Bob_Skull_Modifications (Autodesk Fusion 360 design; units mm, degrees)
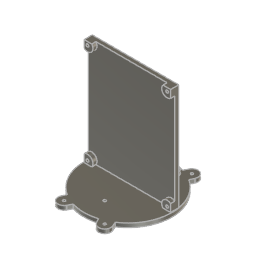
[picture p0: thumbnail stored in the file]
sketch "Bottom" plane through (0, 0, 0) normal (0, 0, 1) x axis (1, 0, 0)
  line L1 (-14.7916, -31.7208) -> (0, 0)
  line L2 (50, 0) -> (0, 0)
  line L3 (-8.961, -31.2402) -> (-10.3196, -33.9571)
  line L4 (-18.1121, -26.9852) -> (-19.331, -29.6245)
  line L5 (0, 13.6394) -> (0, 0)
  line L6 (12.7532, 0) -> (0, 0)
  line L7 (8.961, -31.2402) -> (10.3196, -33.9571)
  line L8 (18.1121, -26.9852) -> (19.331, -29.6245)
  line L9 (8.961, 31.2402) -> (10.3196, 33.9571)
  line L10 (18.1121, 26.9852) -> (19.331, 29.6245)
  line L11 (-8.961, 31.2402) -> (-10.3196, 33.9571)
  line L12 (-18.1121, 26.9852) -> (-19.331, 29.6245)
  line L13 (-9.4082, -31.0166) -> (-10.7668, -33.7335)
  line L14 (-17.6582, -27.1948) -> (-18.877, -29.8341)
  line L15 (-9.2212, -30.6426) -> (-9.4082, -31.0166)
  line L16 (-17.4782, -26.8051) -> (-17.6582, -27.1948)
  line L17 (17.4782, -26.8051) -> (17.6582, -27.1948)
  line L18 (9.2212, -30.6426) -> (9.4082, -31.0166)
  line L19 (9.4082, -31.0166) -> (10.7668, -33.7335)
  line L20 (17.6582, -27.1948) -> (18.877, -29.8341)
  line L21 (-17.4782, 26.8051) -> (-17.6582, 27.1948)
  line L22 (-9.2212, 30.6426) -> (-9.4082, 31.0166)
  line L23 (9.2212, 30.6426) -> (9.4082, 31.0166)
  line L24 (17.4782, 26.8051) -> (17.6582, 27.1948)
  line L25 (17.6582, 27.1948) -> (18.877, 29.8341)
  line L26 (9.4082, 31.0166) -> (10.7668, 33.7335)
  line L27 (-9.4082, 31.0166) -> (-10.7668, 33.7335)
  line L28 (-17.6582, 27.1948) -> (-18.877, 29.8341)
  line L29 (-31.5, 5.5) -> (31.5, 5.5)
  line L30 (-31.5, 2.5) -> (-31.5, 5.5)
  line L31 (31.5, 2.5) -> (-31.5, 2.5)
  line L32 (31.5, 5.5) -> (31.5, 2.5)
  line L33 (-31.5, 2.5) -> (31.5, 5.5)
  line L34 (31.5, 2.5) -> (-31.5, 5.5)
  line L35 (0, 4) -> (0, 0)
  line L36 (0, 25) -> (0, 0)
  line L37 (-3.5, 27) -> (3.5, 27)
  line L38 (-3.5, 23) -> (-3.5, 27)
  line L39 (3.5, 23) -> (-3.5, 23)
  line L40 (3.5, 27) -> (3.5, 23)
  line L41 (-3.5, 23) -> (3.5, 27)
  line L42 (3.5, 23) -> (-3.5, 27)
  line L43 (5.5, 21) -> (-5.5, 21)
  line L44 (5.5, 29) -> (5.5, 21)
  line L45 (-5.5, 29) -> (5.5, 29)
  line L46 (-5.5, 21) -> (-5.5, 29)
  line L47 (-7.5, 25) -> (0, 25)
  line L48 (0, 31) -> (0, 32)
  line L49 (0, -17) -> (0, 0)
  curve K1
  curve K2
  curve K3
  curve K4
  curve K5
  curve K6
  curve K7
  curve K8
  circle C1 centre (0, 0) radius 32.5
  circle C2 centre (-14.7916, -31.7208) radius 5
  circle C3 centre (-14.7916, -31.7208) radius 0.9
  circle C4 centre (14.7916, -31.7208) radius 5
  circle C5 centre (14.7916, -31.7208) radius 0.9
  circle C6 centre (14.7916, 31.7208) radius 5
  circle C7 centre (14.7916, 31.7208) radius 0.9
  circle C8 centre (-14.7916, 31.7208) radius 5
  circle C9 centre (-14.7916, 31.7208) radius 0.9
  circle C10 centre (0, 0) radius 32
  circle C11 centre (-14.7916, -31.7208) radius 4.5
  circle C12 centre (14.7916, -31.7208) radius 4.5
  circle C13 centre (14.7916, 31.7208) radius 4.5
  circle C14 centre (-14.7916, 31.7208) radius 4.5
  circle C15 centre (-7.5, 25) radius 1
  circle C16 centre (7.5, 25) radius 1
  circle C17 centre (-7.5, 25) radius 4
  circle C18 centre (7.5, 25) radius 4
  circle C19 centre (0, 31) radius 2
  circle C20 centre (0, -17) radius 12.5
  circle C21 centre (0, -17) radius 1
  point P1 (0, 0)
  point P2 (0, 0)
  point P3 (0, 0)
  point P4 (-14.7916, -31.7208)
  point P6 (-14.7916, -31.7208)
  point P8 (-10.3196, -33.9571)
  point P9 (-8.961, -31.2402)
  point P10 (-19.331, -29.6245)
  point P11 (-18.1121, -26.9852)
  point P12 (0, 0)
  point P14 (0, 0)
  point P15 (12.7532, 0)
  point P17 (10.3196, -33.9571)
  point P18 (8.961, -31.2402)
  point P19 (19.331, -29.6245)
  point P20 (18.1121, -26.9852)
  point P28 (-10.3196, 33.9571)
  point P29 (-8.961, 31.2402)
  point P32 (-19.331, 29.6245)
  point P33 (-18.1121, 26.9852)
  point P23 (10.3196, 33.9571)
  point P24 (8.961, 31.2402)
  point P25 (19.331, 29.6245)
  point P26 (18.1121, 26.9852)
  point P40 (-9.2212, -30.6426)
  point P41 (-17.4782, -26.8051)
  point P36 (-10.7668, -33.7335)
  point P46 (10.7668, -33.7335)
  point P37 (-9.4082, -31.0166)
  point P44 (9.4082, -31.0166)
  point P38 (-18.877, -29.8341)
  point P48 (18.877, -29.8341)
  point P39 (-17.6582, -27.1948)
  point P42 (17.6582, -27.1948)
  point P45 (9.2212, -30.6426)
  point P43 (17.4782, -26.8051)
  point P60 (-10.7668, 33.7335)
  point P51 (-9.4082, 31.0166)
  point P62 (-18.877, 29.8341)
  point P49 (-17.6582, 27.1948)
  point P52 (-9.2212, 30.6426)
  point P50 (-17.4782, 26.8051)
  point P55 (17.6582, 27.1948)
  point P56 (17.4782, 26.8051)
  point P53 (9.4082, 31.0166)
  point P54 (9.2212, 30.6426)
  point P59 (10.7668, 33.7335)
  point P57 (18.877, 29.8341)
  point P67 (0, 4)
  point P68 (0, 0)
  point P69 (0, 4)
  point P70 (0, 0)
  point P76 (0, 25)
  point P71 (0, 25)
  point P81 (0, 25)
  point P82 (-7.5, 25)
  point P83 (-7.5, 25)
  point P88 (0, 32)
  point P87 (0, 31)
  point P89 (0, 31)
  point P90 (0, 0)
  point P91 (0, -17)
  point P92 (0, -17)
  point P65 (-31.5, 2.5)
  point P66 (31.5, 2.5)
  point P64 (-31.5, 5.5)
  point P74 (-3.5, 23)
  point P75 (3.5, 23)
  point P73 (-3.5, 27)
  coincident P1 P2
  horizontal L2
  coincident P2 P3
  coincident P4 P6
  concentric C2 C3
  coincident C2 P8
  coincident C1 P9
  tangent C2 L3
  coincident C2 P10
  coincident C1 P11
  tangent C2 L4
  coincident P2 P12
  perpendicular L2 L5
  coincident P2 P14
  coincident L2 P15
  symmetric C2 L5 C4
  symmetric C3 L5 C5
  symmetric P8 L5 P17
  symmetric P9 L5 P18
  symmetric P10 L5 P19
  symmetric P11 L5 P20
  symmetric C2 L6 C8
  symmetric C3 L6 C9
  symmetric P8 L6 P28
  symmetric P9 L6 P29
  symmetric P10 L6 P32
  symmetric P11 L6 P33
  symmetric L6 C4 C6
  symmetric L6 P17 P23
  symmetric L6 P18 P24
  symmetric L6 P19 P25
  symmetric L6 P20 P26
  symmetric L6 C5 C7
  coincident C10 P40
  parallel L13 L15
  coincident C10 P41
  parallel L14 L16
  symmetric L5 C11 C12
  symmetric L5 P36 P46
  symmetric L5 P37 P44
  symmetric L5 P38 P48
  symmetric L5 P39 P42
  symmetric L5 P40 P45
  symmetric L5 P41 P43
  symmetric L2 C11 C14
  symmetric L2 P36 P60
  symmetric L2 P37 P51
  symmetric L2 P38 P62
  symmetric L2 P39 P49
  symmetric L2 P40 P52
  symmetric L2 P41 P50
  symmetric L2 P42 P55
  symmetric L2 P43 P56
  symmetric L2 P44 P53
  symmetric L2 P45 P54
  symmetric L2 P46 P59
  symmetric L2 C12 C13
  symmetric L2 P48 P57
  horizontal L29
  perpendicular L29 L30
  parallel L29 L31
  parallel L30 L32
  coincident L33 P67
  coincident L34 P67
  coincident P2 P68
  coincident P67 P69
  perpendicular L31 L35
  coincident P1 P70
  perpendicular L2 L36
  horizontal L37
  perpendicular L37 L38
  parallel L37 L39
  parallel L38 L40
  coincident L41 P76
  coincident L42 P76
  coincident P71 P76
  coincident P76 P81
  perpendicular L46 L47
  coincident P82 P83
  symmetric L36 C15 C16
  symmetric L36 C17 C18
  coincident C10 P88
  coincident P87 P89
  vertical L48
  tangent L45 C19
  coincident P1 P90
  perpendicular L6 L49
  coincident P91 P92
  concentric C20 C21
  dimension "d1" diameter C1 = 65
  dimension "d18" angle L1 L2 = 115 (= "90 deg + 25 deg")
  dimension "d19" distance P3 P4 = 35
  dimension "d20" diameter C2 = 10
  dimension "d21" diameter C3 = 1.8
  dimension "d27" = -0.5
  dimension "d28" = -0.5
  dimension "d29" = -0.5
  dimension "d30" = 0.5
  dimension "d33" distance P65 P66 = 63
  dimension "d34" distance P64 P65 = 3
  dimension "d35" distance P68 P69 = 4
  dimension "d55" distance P70 P71 = 25
  dimension "d56" distance P74 P75 = 7
  dimension "d57" distance P73 P74 = 4
  dimension "d58" = 2
  dimension "d59" distance P81 P82 = 7.5 (= "( 15 / 2 ) * 1 mm")
  dimension "d60" diameter C15 = 2
  dimension "d61" = 3
  dimension "d74" diameter C19 = 4
  dimension "d75" distance P90 P91 = 17
  dimension "d76" diameter C20 = 25
  dimension "d77" diameter C21 = 2
  dimension "d81" Text1-Height = 4
  dimension "d83" Text2-Height = 4
extrude "Extrude1" new body sketch "Bottom" profile of C1 along normal blind 134 bodies "Opening"
fillet "Fillet1" radius 32.5 (= "d1 / 2")
sketch "Eyes" plane through (0, 0, 0) normal (0, 1, 0) x axis (1, 0, 0)
  line L1 (0, -80) -> (0, 0)
  line L2 (-30, -80) -> (0, -80)
  line L3 (22, -80) -> (0, -80)
  circle C1 centre (-30, -80) radius 3.5
  circle C2 centre (22, -80) radius 3.5
  point P1 (0, 0)
  point P2 (0, 0)
  point P4 (-30, -80)
  point P5 (-30, -80)
  point P6 (22, -80)
  point P7 (22, -80)
  point P3 (0, -80)
  coincident P1 P2
  vertical L1
  perpendicular L1 L2
  coincident P4 P5
  perpendicular L1 L3
  coincident P6 P7
  dimension "d6" distance P2 P3 = 80
  dimension "d7" distance P3 P4 = 30
  dimension "d8" diameter C1 = 7
  dimension "d14" distance P3 P6 = 22
  dimension "d15" diameter C2 = 7 (= "d8")
extrude "Extrude2" add sketch "Eyes" profile of C1 C2 blind 50 from offset -50
fillet "Fillet3" radius 10
extrude "Extrude3" add sketch "Bottom" profile of C1 L1 C2 C3 L3 L4 C4 L7 L8 C5 C6 L9 L10 C7 L11 C8 C9 L12 along normal blind 4
extrude "Extrude4" sketch "Bottom" profile of C3 C5 C7 C9 blind 10
extrude "Extrude5" new body sketch "Bottom" profile of C1 L1 C2 C3 C4 C5 C6 C7 C8 C9 C10 C11 L13 L14 L15 L16 L17 L18 L19 C12 L20 L21 L22 L23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 along normal blind 3 bodies "Cover/Mount"
extrude "Extrude6" sketch "Bottom" profile of L5 L29 L30 L31 L32 L35 blind 77.5
sketch "Mount" plane through (0, 0, 0) normal (0, 1, 0) x axis (1, 0, 0)
  line L1 (31.5, -80.5) -> (-31.5, -80.5)
  line L2 (31.5, -3) -> (31.5, -80.5)
  line L3 (-31.5, -3) -> (31.5, -3)
  line L4 (-31.5, -80.5) -> (-31.5, -3)
  line L5 (31.5, -3) -> (-31.5, -80.5)
  line L6 (31.5, -80.5) -> (-31.5, -3)
  line L7 (5.3781, -41.75) -> (0, -41.75)
  line L8 (0, -32.3074) -> (0, -41.75)
  line L9 (-23.25, -3.25) -> (23.25, -3.25)
  line L10 (-23.25, -60.25) -> (-23.25, -3.25)
  line L11 (23.25, -60.25) -> (-23.25, -60.25)
  line L12 (23.25, -3.25) -> (23.25, -60.25)
  line L13 (-23.25, -60.25) -> (23.25, -3.25)
  line L14 (23.25, -60.25) -> (-23.25, -3.25)
  line L15 (0, -31.75) -> (0, -41.75)
  line L16 (-15, -31.75) -> (0, -31.75)
  circle C1 centre (-29, -78) radius 1
  circle C2 centre (29, -78) radius 1
  circle C3 centre (29, -5.5) radius 1
  circle C4 centre (-29, -5.5) radius 1
  circle C5 centre (-29, -5.5) radius 4
  circle C6 centre (29, -5.5) radius 4
  circle C7 centre (-29, -78) radius 4
  circle C8 centre (29, -78) radius 4
  circle C9 centre (-15, -31.75) radius 1
  circle C10 centre (15, -31.75) radius 1
  point P4 (31.5, -3)
  point P7 (31.5, -3)
  point P2 (-31.5, -80.5)
  point P6 (-31.5, -80.5)
  point P8 (-31.5, -80.5)
  point P9 (31.5, -3)
  point P10 (0, -41.75)
  point P27 (0, -31.75)
  point P28 (0, -31.75)
  point P29 (0, -31.75)
  point P30 (-15, -31.75)
  point P31 (-15, -31.75)
  point P25 (-23.25, -60.25)
  point P26 (23.25, -60.25)
  point P24 (-23.25, -3.25)
  point P11 (0, -41.75)
  horizontal L1
  vertical L2
  horizontal L3
  vertical L4
  coincident P4 P7
  coincident P2 P6
  coincident P6 P8
  coincident P7 P9
  midpoint L6 P10
  vertical L8
  perpendicular L7 L8
  symmetric L8 C3 C4
  symmetric L8 C5 C6
  symmetric C1 L7 C4
  symmetric L7 C5 C7
  symmetric L7 C6 C8
  symmetric C2 L7 C3
  horizontal L9
  perpendicular L9 L10
  parallel L9 L11
  parallel L10 L12
  coincident L13 P27
  coincident L14 P27
  coincident P27 P28
  parallel L8 L15
  coincident P27 P29
  horizontal L16
  coincident P30 P31
  symmetric L15 C9 C10
  dimension "d39" = 3
  dimension "d40" diameter C4 = 2
  dimension "d47" distance P25 P26 = 46.5
  dimension "d48" distance P24 P25 = 57
  dimension "d49" distance P11 P28 = 10
  dimension "d50" distance P29 P30 = 15
  dimension "d51" diameter C9 = 2 (= "d40")
extrude "Extrude7" sketch "Mount" profile of L1 L2 L3 L4 L5 L6 C1 C2 C3 C4 C6 C7 C8 C5 blind -3
extrude "Extrude8" sketch "Mount" profile of L5 L6 C1 C2 C3 C4 blind 5
extrude "Extrude9" sketch "Mount" profile of C9 C10 blind -2
extrude "Extrude10" sketch "Bottom" profile of C10 L36 L37 L38 L39 L40 L47 C19 C21 to an object
extrude "Extrude11" sketch "Bottom" profile of L44 L46 L47 C15 C16 C17 C18 blind 2.5 (= "5 mm - 2 mm - 0.5 mm")
extrude "Extrude12" sketch "Bottom" profile of L36 L37 L38 L39 L40 L43 L44 L45 L46 L47 C17 C18 blind 1
chamfer "Chamfer1" distance 1.2
fillet "Fillet4" radius 2
extrude "Extrude13" sketch "Bottom" profile of L1 L49 C20 C21 blind 0.8
extrude "Extrude14" sketch "Bottom" blind -0.4
named bodies: "Opening", "Cover/Mount"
